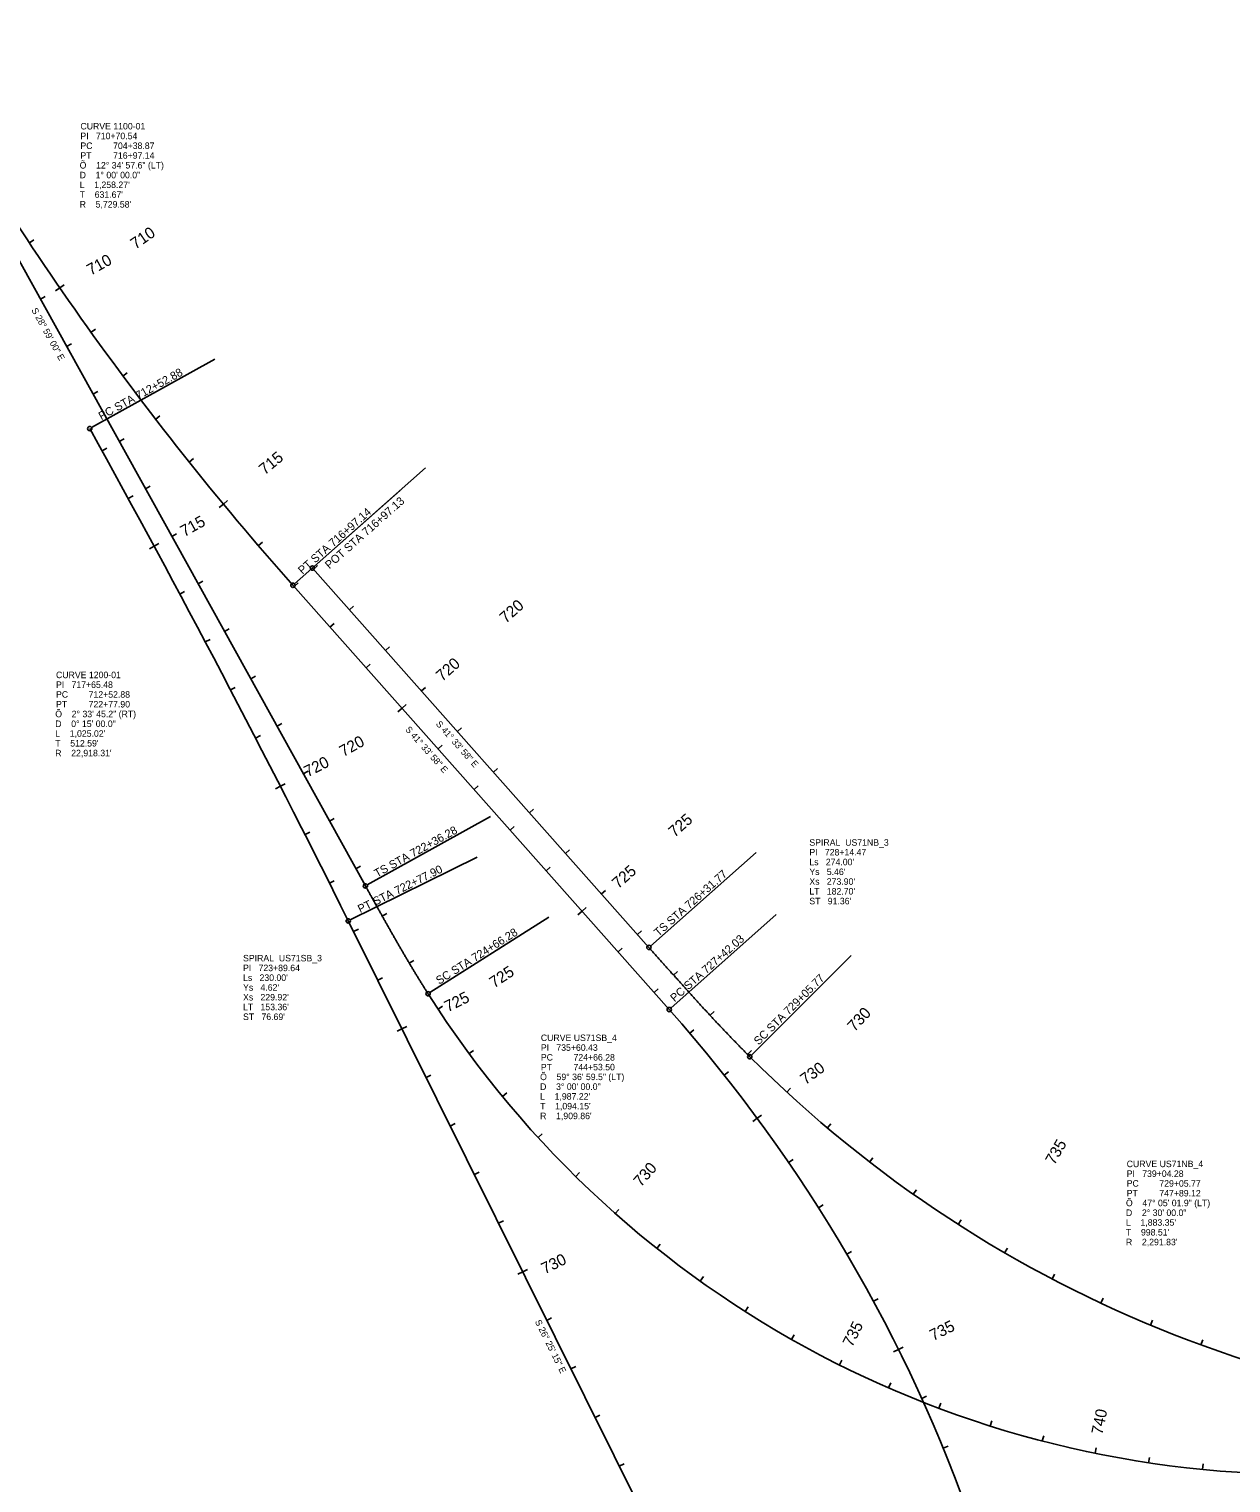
# Model space of a CAD drawing. Extents: x 2819977 to 2827606, y 113942 to 150283.
# Drawn here: x 2821927 to 2824142, y 145308 to 147987 of the extents above; entities that cross this region are included whole.
import ezdxf

# ---------------------------------------------------------------- set-up
doc = ezdxf.new("R2010")
doc.units = 0
for name, color, linetype in [('Level 63', 7, 'Continuous'), ('Roadway-Safety', 7, 'Continuous'), ('Roadway-Signs', 7, 'Continuous'), ('Roadway-Walls', 7, 'Continuous'), ('Utility-Power', 7, 'Continuous')]:
    doc.layers.add(name, color=color, linetype=linetype)

msp = doc.modelspace()

# ---------------------------------------------------------------- linework, layer by layer
at = {"layer": 'Level 63'}
for centre in [(2822413.7, 146961.8), (2822547.2, 146407.9), (2823069.7, 146294.4), (2822662.6, 146209), (2823107, 146180), (2823255.5, 146093.1)]:
    msp.add_circle(centre, 4, dxfattribs=at)
at = {"layer": 'Roadway-Safety'}
for p, q in [((2822042.7, 147252.6), (2822269.9, 147378.5)), ((2822452.6, 146996.3), (2822658.2, 147178.6)), ((2822416.7, 146964.5), (2822611, 147136.8)), ((2822451.5, 146991.5), (2822459, 146998.2)), ((2822449.6, 146993.7), (2823069.7, 146294.4)), ((2822517.9, 146916.7), (2822525.3, 146923.3)), ((2822584.2, 146841.9), (2822591.7, 146848.5)), ((2822650.6, 146767.1), (2822658, 146773.7)), ((2822716.9, 146692.2), (2822724.4, 146698.9)), ((2822783.2, 146617.4), (2822790.7, 146624.1)), ((2822849.6, 146542.6), (2822857.1, 146549.2)), ((2822550.7, 146409.8), (2822777.9, 146535.7)), ((2822519.2, 146345), (2822752.9, 146461.1)), ((2822915.9, 146467.8), (2822923.4, 146474.4)), ((2823072.7, 146297), (2823267.1, 146469.4)), ((2822982.3, 146393), (2822989.8, 146399.6)), ((2823110, 146182.7), (2823304.3, 146355)), ((2822666, 146211.2), (2822885.3, 146350.5)), ((2823048.6, 146318.1), (2823056.1, 146324.8)), ((2823258.4, 146095.9), (2823442.1, 146279.5))]:
    msp.add_line(p, q, dxfattribs=at)
msp.add_circle((2822449.6, 146993.7), 4, dxfattribs=at)
at = {"layer": 'Utility-Power'}
for p, q in [((2821676.3, 147980.2), (2822547.2, 146407.9)), ((2821927.9, 147593), (2821936.3, 147598.6)), ((2821984, 147510.2), (2821975.8, 147504.6)), ((2821984, 147510.2), (2821992.2, 147515.9)), ((2821948.2, 147489.4), (2821956.9, 147494.2)), ((2822041.5, 147428.4), (2822049.6, 147434.2)), ((2821996.6, 147401.9), (2822005.4, 147406.7)), ((2822100.4, 147347.6), (2822108.4, 147353.6)), ((2822045.1, 147314.4), (2822053.8, 147319.3)), ((2822160.7, 147267.8), (2822168.6, 147273.9)), ((2822062, 147209.5), (2822070.7, 147214.3)), ((2822093.5, 147226.9), (2822102.3, 147231.8)), ((2822222.4, 147189.1), (2822230.2, 147195.4)), ((2822142, 147139.5), (2822150.7, 147144.3)), ((2822110.1, 147121.8), (2822118.9, 147126.6)), ((2822285.5, 147111.5), (2822277.7, 147105.2)), ((2822285.5, 147111.5), (2822293.2, 147117.9)), ((2822190.4, 147052), (2822199.2, 147056.8)), ((2822157.8, 147033.9), (2822149, 147029.1)), ((2822157.8, 147033.9), (2822166.6, 147038.6)), ((2822349.9, 147035), (2822357.5, 147041.5)), ((2822238.9, 146964.5), (2822247.6, 146969.3)), ((2822205.1, 146945.8), (2822213.9, 146950.5)), ((2822413.7, 146961.8), (2823107, 146180)), ((2822415.6, 146959.7), (2822423.1, 146966.3)), ((2822481.9, 146884.9), (2822489.4, 146891.5)), ((2822252, 146857.5), (2822260.9, 146862.2)), ((2822287.3, 146877), (2822296.1, 146881.9)), ((2822548.3, 146810), (2822555.8, 146816.7)), ((2822335.8, 146789.5), (2822344.5, 146794.4)), ((2822298.6, 146769), (2822307.4, 146773.6)), ((2822614.6, 146735.2), (2822607.2, 146728.6)), ((2822614.6, 146735.2), (2822622.1, 146741.9)), ((2822384.3, 146702.1), (2822393, 146706.9)), ((2822344.7, 146680.3), (2822353.6, 146684.9)), ((2822681, 146660.4), (2822688.5, 146667)), ((2822390.5, 146591.4), (2822399.4, 146595.9)), ((2822432.7, 146614.6), (2822441.5, 146619.4)), ((2822390.5, 146591.4), (2822381.6, 146586.8)), ((2822747.3, 146585.6), (2822754.8, 146592.2)), ((2822481.2, 146527.1), (2822489.9, 146532)), ((2822813.7, 146510.8), (2822821.2, 146517.4)), ((2822435.9, 146502.3), (2822444.8, 146506.8)), ((2822529.6, 146439.6), (2822538.4, 146444.5)), ((2822880, 146435.9), (2822887.5, 146442.6)), ((2822480.9, 146413), (2822489.8, 146417.4)), ((2822578.2, 146352.2), (2822586.9, 146357.1)), ((2822946.4, 146361.1), (2822938.9, 146354.5)), ((2822946.4, 146361.1), (2822953.9, 146367.8)), ((2822515.7, 146343.3), (2823322.4, 144719.6)), ((2822525.5, 146323.5), (2822534.5, 146327.9)), ((2823012.7, 146286.3), (2823020.2, 146292.9)), ((2822628, 146265.5), (2822636.6, 146270.6)), ((2823115.1, 146243.4), (2823122.5, 146250)), ((2822570, 146233.9), (2822578.9, 146238.4)), ((2822662.6, 146209), (2822662.6, 146209)), ((2823079.1, 146211.5), (2823086.6, 146218.1)), ((2822681, 146180.7), (2822689.3, 146186.2)), ((2823182.3, 146169.4), (2823189.6, 146176.2)), ((2822614.5, 146144.3), (2822605.5, 146139.9)), ((2822614.5, 146144.3), (2822623.4, 146148.8)), ((2823145, 146136.3), (2823152.6, 146142.8)), ((2822738.3, 146098.8), (2822746.3, 146104.7)), ((2823251.5, 146097.2), (2823258.6, 146104.2)), ((2823255.5, 146093.1), (2823255.5, 146093.1)), ((2822659, 146054.8), (2822667.9, 146059.2)), ((2823208.5, 146059), (2823216.3, 146065.2)), ((2823323.5, 146027.8), (2823330.3, 146035.2)), ((2822799.7, 146019.9), (2822807.5, 146026.3)), ((2823269.2, 145979.6), (2823261.2, 145973.7)), ((2823269.2, 145979.6), (2823277.3, 145985.5)), ((2822703.5, 145965.2), (2822712.4, 145969.7)), ((2823398.5, 145961.7), (2823405, 145969.3)), ((2822865.3, 145944.4), (2822872.6, 145951.1)), ((2823327.1, 145898.1), (2823335.4, 145903.7)), ((2823476.3, 145898.9), (2823482.4, 145906.8)), ((2822748, 145875.7), (2822756.9, 145880.1)), ((2822934.7, 145872.4), (2822941.7, 145879.5)), ((2823556.8, 145839.5), (2823562.6, 145847.7)), ((2823382.2, 145814.6), (2823390.6, 145820)), ((2822792.5, 145786.1), (2822801.4, 145790.6)), ((2823007.7, 145804.1), (2823014.3, 145811.6)), ((2823639.8, 145783.8), (2823645.2, 145792.2)), ((2823084.2, 145739.8), (2823090.5, 145747.6)), ((2823725.1, 145731.7), (2823730.2, 145740.3)), ((2823434.3, 145729.3), (2823442.9, 145734.3)), ((2822837, 145696.6), (2822828, 145692.1)), ((2822837, 145696.6), (2822845.9, 145701)), ((2823164, 145679.5), (2823169.9, 145687.7)), ((2823812.7, 145683.3), (2823817.3, 145692.2)), ((2823246.9, 145623.5), (2823252.3, 145632)), ((2823483.4, 145642.2), (2823492.2, 145646.9)), ((2823902.2, 145638.9), (2823906.5, 145647.9)), ((2822881.5, 145607), (2822890.4, 145611.5)), ((2823993.7, 145598.4), (2823997.5, 145607.6)), ((2823332.5, 145572), (2823337.5, 145580.7)), ((2823529.4, 145553.4), (2823520.5, 145548.9)), ((2823529.4, 145553.4), (2823538.4, 145557.8)), ((2824086.8, 145561.9), (2824090.2, 145571.3)), ((2823420.8, 145524.9), (2823425.3, 145533.9)), ((2822926, 145517.5), (2822934.9, 145521.9)), ((2823511.4, 145482.6), (2823515.4, 145491.8)), ((2823572.3, 145463.1), (2823581.4, 145467.2)), ((2823604, 145445), (2823607.5, 145454.4)), ((2822970.5, 145427.9), (2822979.4, 145432.4)), ((2823698.5, 145412.4), (2823701.6, 145421.9)), ((2823794.6, 145384.8), (2823797.1, 145394.4)), ((2823612.1, 145371.3), (2823621.3, 145375.1)), ((2823892, 145362.2), (2823894, 145372)), ((2823015, 145338.4), (2823023.9, 145342.8)), ((2823990.5, 145344.7), (2823992, 145354.6)), ((2824089.7, 145332.4), (2824090.7, 145342.4))]:
    msp.add_line(p, q, dxfattribs=at)
for centre in [(2822039.2, 147250.7), (2822515.7, 146343.3)]:
    msp.add_circle(centre, 4, dxfattribs=at)
for centre, radius, start, end in [((2826700.5, 150763.3), 5729.6, 208.9835, 221.5661), ((2801991.2, 136145.5), 22918.3, 26.42092, 28.98346), ((2824274.6, 147233.3), 1909.9, 212.4335, 272.05), ((2820963.6, 144279.3), 2864.8, 356.8489, 41.5661), ((2824876.4, 147713.4), 2291.8, 224.9911, 272.075)]:
    msp.add_arc(centre, radius, start, end, dxfattribs=at)
for points in [[(2822547.2, 146407.9), (2822548.7, 146405.2), (2822550.2, 146402.5), (2822551.7, 146399.8), (2822553.2, 146397), (2822554.7, 146394.3), (2822556.2, 146391.6), (2822557.7, 146388.9), (2822559.3, 146386.2), (2822560.8, 146383.4), (2822562.3, 146380.7), (2822563.8, 146378), (2822565.3, 146375.3), (2822566.8, 146372.6), (2822568.3, 146369.9), (2822569.8, 146367.1), (2822571.3, 146364.4), (2822572.9, 146361.7), (2822574.4, 146359), (2822575.9, 146356.3), (2822577.4, 146353.6), (2822578.9, 146350.9), (2822580.4, 146348.2), (2822582, 146345.4), (2822583.5, 146342.7), (2822585, 146340), (2822586.5, 146337.3), (2822588.1, 146334.6), (2822589.6, 146331.9), (2822591.1, 146329.2), (2822592.7, 146326.5), (2822594.2, 146323.8), (2822595.7, 146321.1), (2822597.3, 146318.4), (2822598.8, 146315.7), (2822600.3, 146313), (2822601.9, 146310.3), (2822603.4, 146307.6), (2822605, 146304.9), (2822606.5, 146302.2), (2822608.1, 146299.5), (2822609.6, 146296.8), (2822611.2, 146294.1), (2822612.8, 146291.4), (2822614.3, 146288.8), (2822615.9, 146286.1), (2822617.4, 146283.4), (2822619, 146280.7), (2822620.6, 146278), (2822622.2, 146275.3), (2822623.7, 146272.7), (2822625.3, 146270), (2822626.9, 146267.3), (2822628.5, 146264.6), (2822630.1, 146262), (2822631.7, 146259.3), (2822633.3, 146256.6), (2822634.9, 146254), (2822636.5, 146251.3), (2822638.1, 146248.7), (2822639.7, 146246), (2822641.3, 146243.3), (2822642.9, 146240.7), (2822644.6, 146238), (2822646.2, 146235.4), (2822647.8, 146232.7), (2822649.4, 146230.1), (2822651.1, 146227.4), (2822652.7, 146224.8), (2822654.4, 146222.2), (2822656, 146219.5), (2822657.7, 146216.9), (2822659.3, 146214.3), (2822661, 146211.6), (2822662.6, 146209)], [(2823069.7, 146294.4), (2823072.2, 146291.6), (2823074.6, 146288.8), (2823077.1, 146286.1), (2823079.5, 146283.3), (2823082, 146280.5), (2823084.5, 146277.8), (2823086.9, 146275), (2823089.4, 146272.2), (2823091.8, 146269.5), (2823094.3, 146266.7), (2823096.8, 146263.9), (2823099.2, 146261.1), (2823101.7, 146258.4), (2823104.1, 146255.6), (2823106.6, 146252.9), (2823109.1, 146250.1), (2823111.5, 146247.3), (2823114, 146244.6), (2823116.5, 146241.8), (2823118.9, 146239), (2823121.4, 146236.3), (2823123.9, 146233.5), (2823126.3, 146230.8), (2823128.8, 146228), (2823131.3, 146225.3), (2823133.8, 146222.5), (2823136.3, 146219.8), (2823138.7, 146217), (2823141.2, 146214.3), (2823143.7, 146211.5), (2823146.2, 146208.8), (2823148.7, 146206), (2823151.2, 146203.3), (2823153.6, 146200.5), (2823156.1, 146197.8), (2823158.6, 146195.1), (2823161.1, 146192.3), (2823163.6, 146189.6), (2823166.1, 146186.9), (2823168.6, 146184.1), (2823171.1, 146181.4), (2823173.6, 146178.7), (2823176.2, 146176), (2823178.7, 146173.2), (2823181.2, 146170.5), (2823183.7, 146167.8), (2823186.2, 146165.1), (2823188.8, 146162.4), (2823191.3, 146159.7), (2823193.8, 146157), (2823196.3, 146154.3), (2823198.9, 146151.6), (2823201.4, 146148.9), (2823204, 146146.2), (2823206.5, 146143.5), (2823209.1, 146140.8), (2823211.6, 146138.1), (2823214.2, 146135.5), (2823216.7, 146132.8), (2823219.3, 146130.1), (2823221.8, 146127.4), (2823224.4, 146124.8), (2823227, 146122.1), (2823229.6, 146119.5), (2823232.1, 146116.8), (2823234.7, 146114.1), (2823237.3, 146111.5), (2823239.9, 146108.9), (2823242.5, 146106.2), (2823245.1, 146103.6), (2823247.7, 146100.9), (2823250.3, 146098.3), (2823252.9, 146095.7), (2823255.5, 146093.1)]]:
    msp.add_spline(points, degree=3, dxfattribs=at)

# ---------------------------------------------------------------- texts
at = {"layer": 'Roadway-Safety'}
for s, height, rotation, p in [('S 28%%d 59\' 00" E', 12, 298.9835, (2821931.2, 147469.1)), ('PC STA 712+52.88', 15, 28.9835, (2822060.5, 147265.9)), ('PT STA 716+97.14', 15, 41.5661, (2822431.2, 146981.3)), ('POT STA 716+97.13', 15, 41.5661, (2822480.8, 146991.1)), (' 720', 21, 41.5661, (2822800.1, 146885.6)), ('S 41%%d 33\' 58" E', 12, 311.5661, (2822676.2, 146705.6)), (' 725', 21, 41.5661, (2823111.1, 146491.1)), ('TS STA 722+36.28', 15, 28.9835, (2822568.5, 146423.1)), ('PT STA 722+77.90', 15, 26.4209, (2822537.6, 146357.5)), ('TS STA 726+31.77', 15, 41.5661, (2823087.2, 146313.9)), ('SC STA 724+66.28', 15, 32.4335, (2822683, 146225.5)), ('PC STA 727+42.03', 15, 41.5661, (2823117, 146193.1)), ('SC STA 729+05.77', 15, 44.9911, (2823271.8, 146113.6))]:
    msp.add_text(s, height=height, rotation=rotation, dxfattribs=at).set_placement(p)
at = {"layer": 'Roadway-Signs'}
for s, rotation, p in [('S 41%%d 33\' 58" E', 311.5661, (2822619.8, 146695.5)), ('S 26%%d 25\' 15" E', 296.4209, (2822859.1, 145604.8))]:
    msp.add_text(s, height=12, rotation=rotation, dxfattribs=at).set_placement(p)
at = {"layer": 'Roadway-Walls'}
for s, p in [('CURVE 1100-01', (2822022, 147802)), ('PI   710+70.54', (2822022, 147784)), ('PC', (2822022, 147766)), ('704+38.87', (2822082.2, 147766)), ('PT', (2822022, 147748)), ('716+97.14', (2822082.2, 147748)), ('Õ    12%%d 34\' 57.6" (LT)', (2822020.6, 147730)), ('D    1%%d 00\' 00.0"', (2822020.6, 147712)), ("L    1,258.27'", (2822020.6, 147694)), ("T    631.67'", (2822020.6, 147676)), ("R    5,729.58'", (2822020.6, 147658)), ('CURVE 1200-01', (2821977, 146790.7)), ('PI   717+65.48', (2821977, 146772.7)), ('PC', (2821977, 146754.7)), ('712+52.88', (2822037.1, 146754.7)), ('Õ    2%%d 33\' 45.2" (RT)', (2821975.6, 146718.7)), ('PT', (2821977, 146736.7)), ('722+77.90', (2822037.1, 146736.7)), ('D    0%%d 15\' 00.0"', (2821975.6, 146700.7)), ("T    512.59'", (2821975.6, 146664.7)), ("L    1,025.02'", (2821975.6, 146682.7)), ("R    22,918.31'", (2821975.6, 146646.7)), ('SPIRAL  US71NB_3', (2823365.3, 146481.9)), ('PI   728+14.47', (2823365.3, 146463.9)), ("Ys   5.46'", (2823365.3, 146427.9)), ("Ls   274.00'", (2823365.3, 146445.9)), ("Xs   273.90'", (2823365.3, 146409.9)), ("ST   91.36'", (2823365.3, 146373.9)), ("LT   182.70'", (2823365.3, 146391.9)), ('SPIRAL  US71SB_3', (2822321.7, 146268.7)), ('PI   723+89.64', (2822321.7, 146250.7)), ("Ys   4.62'", (2822321.7, 146214.7)), ("Ls   230.00'", (2822321.7, 146232.7)), ("Xs   229.92'", (2822321.7, 146196.7)), ("ST   76.69'", (2822321.7, 146160.7)), ("LT   153.36'", (2822321.7, 146178.7)), ('CURVE US71SB_4', (2822870.5, 146121.9)), ('PI   735+60.43', (2822870.5, 146103.9)), ('PC', (2822870.5, 146085.9)), ('724+66.28', (2822930.6, 146085.9)), ('Õ    59%%d 36\' 59.5" (LT)', (2822869.1, 146049.9)), ('PT', (2822870.5, 146067.9)), ('744+53.50', (2822930.6, 146067.9)), ('D    3%%d 00\' 00.0"', (2822869.1, 146031.9)), ("T    1,094.15'", (2822869.1, 145995.9)), ("L    1,987.22'", (2822869.1, 146013.9)), ("R    1,909.86'", (2822869.1, 145977.9)), ('CURVE US71NB_4', (2823950.1, 145889.5)), ('PI   739+04.28', (2823950.1, 145871.5)), ('PC', (2823950.1, 145853.5)), ('PT', (2823950.1, 145835.5)), ('729+05.77', (2824010.2, 145853.5)), ('747+89.12', (2824010.2, 145835.5)), ('Õ    47%%d 05\' 01.9" (LT)', (2823948.7, 145817.5)), ('D    2%%d 30\' 00.0"', (2823948.7, 145799.5)), ("L    1,883.35'", (2823948.7, 145781.5)), ("T    998.51'", (2823948.7, 145763.5)), ("R    2,291.83'", (2823948.7, 145745.5))]:
    msp.add_text(s, height=12, dxfattribs=at).set_placement(p)
at = {"layer": 'Utility-Power'}
for s, rotation, p in [(' 710', 34.5948, (2822117, 147575.8)), (' 710', 28.9835, (2822034.2, 147528.6)), (' 715', 39.5948, (2822355.7, 147159.3)), (' 715', 28.9835, (2822206.5, 147046.8)), (' 720', 41.5661, (2822682.7, 146778.4)), (' 720', 28.9835, (2822499.7, 146641.3)), (' 720', 27.1157, (2822433.8, 146604.2)), (' 725', 41.5661, (2823007.3, 146396.3)), (' 725', 33.445, (2822777.8, 146214.5)), (' 725', 26.4209, (2822692.1, 146171.2)), (' 730', 47.3469, (2823443.4, 146132)), (' 730', 36.4068, (2823351.8, 146035.7)), (' 735', 59.8469, (2823812.8, 145885.5)), (' 730', 48.445, (2823049.5, 145846)), (' 730', 26.4209, (2822870.7, 145688.3)), (' 735', 63.445, (2823440.7, 145549.6)), (' 735', 26.4068, (2823586.4, 145565.3)), (' 740', 78.445, (2823903.6, 145387.8))]:
    msp.add_text(s, height=21, rotation=rotation, dxfattribs=at).set_placement(p)

doc.saveas('drawing.dxf')
